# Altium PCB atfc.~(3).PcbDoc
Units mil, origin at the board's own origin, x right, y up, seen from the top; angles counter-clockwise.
Board outline 6000 x 4000 mil, 2 copper layers (Top Layer, Bottom Layer); 22 components, 0 nets, 5638 pads, 0 vias.
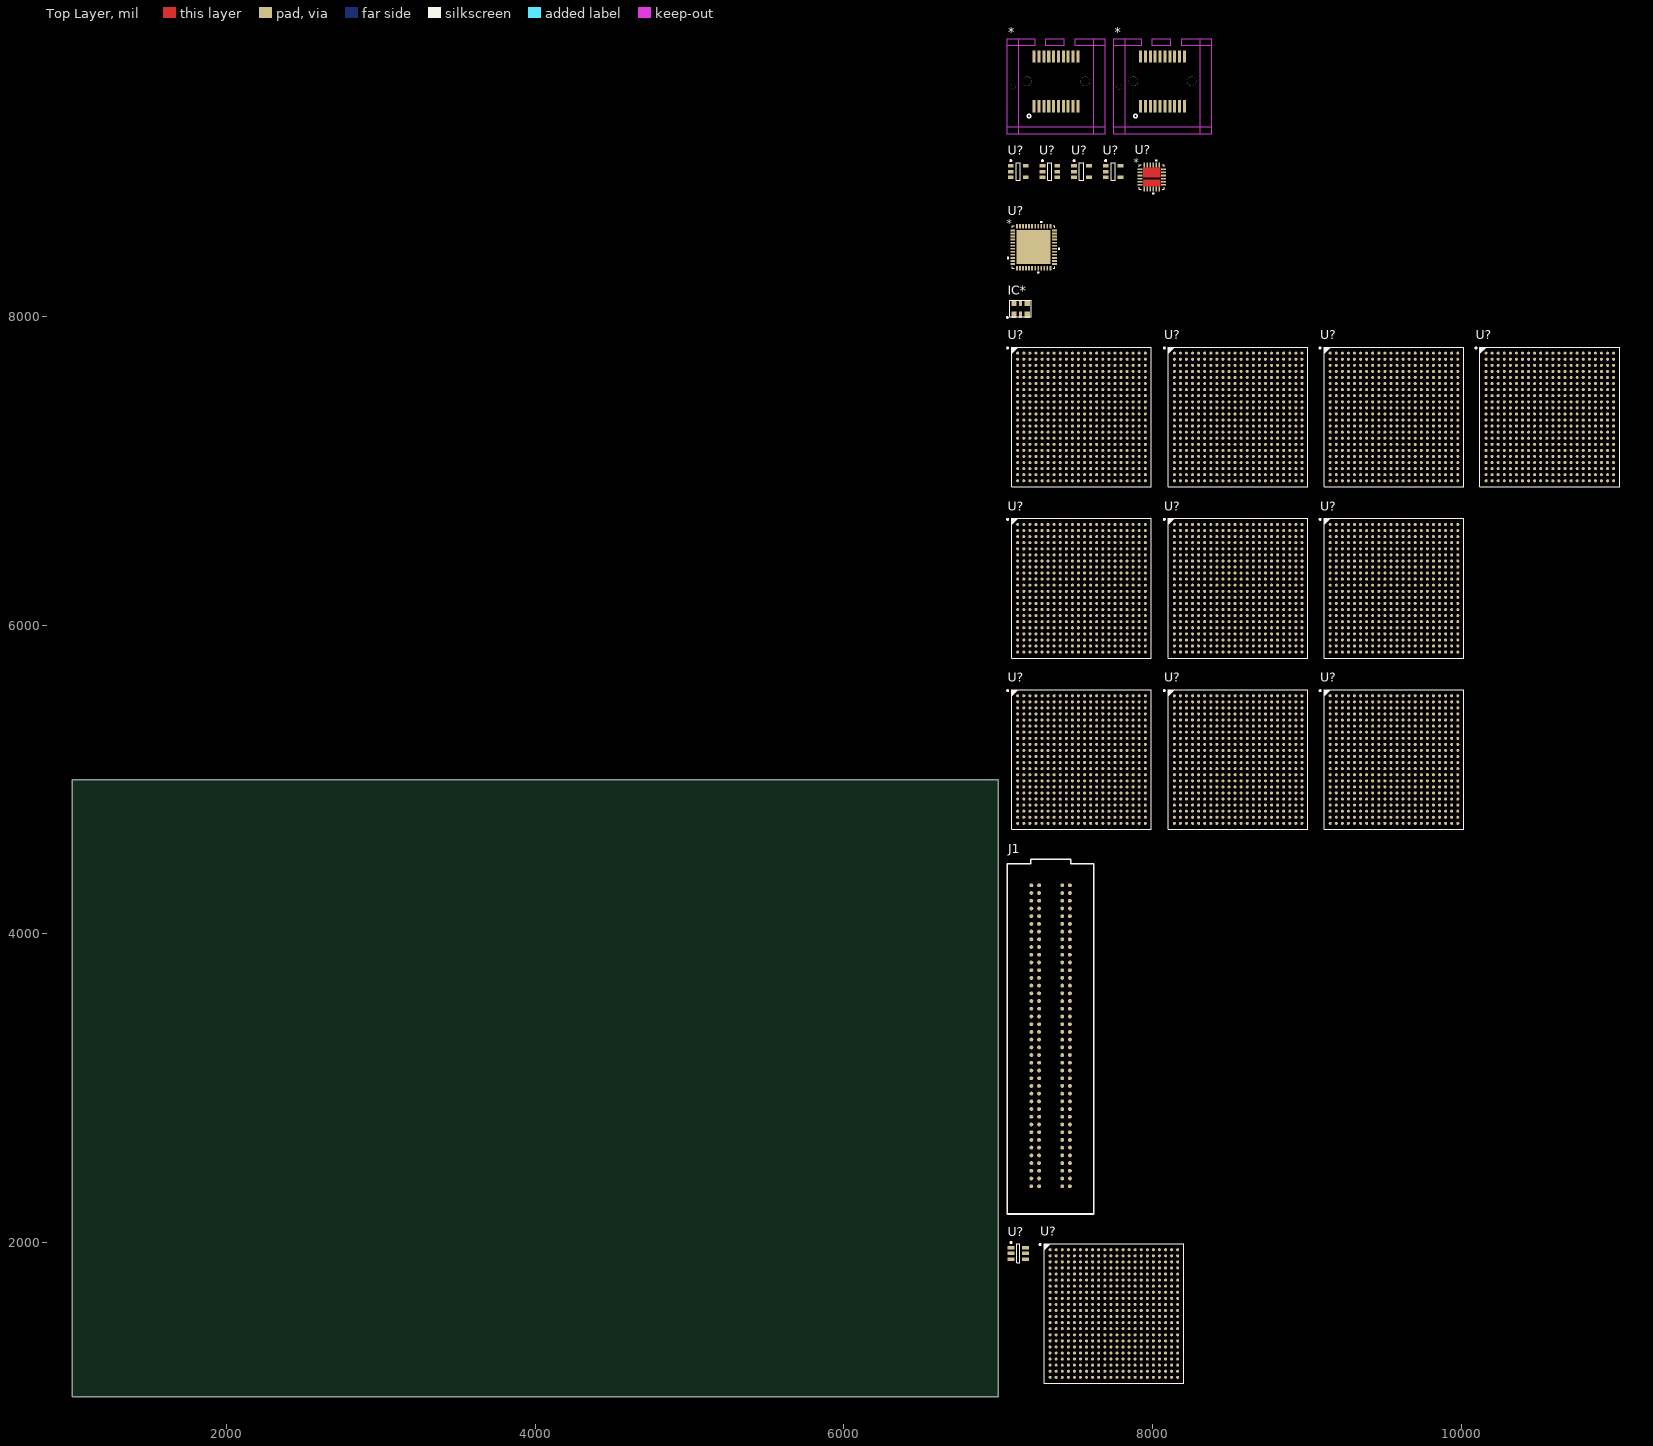
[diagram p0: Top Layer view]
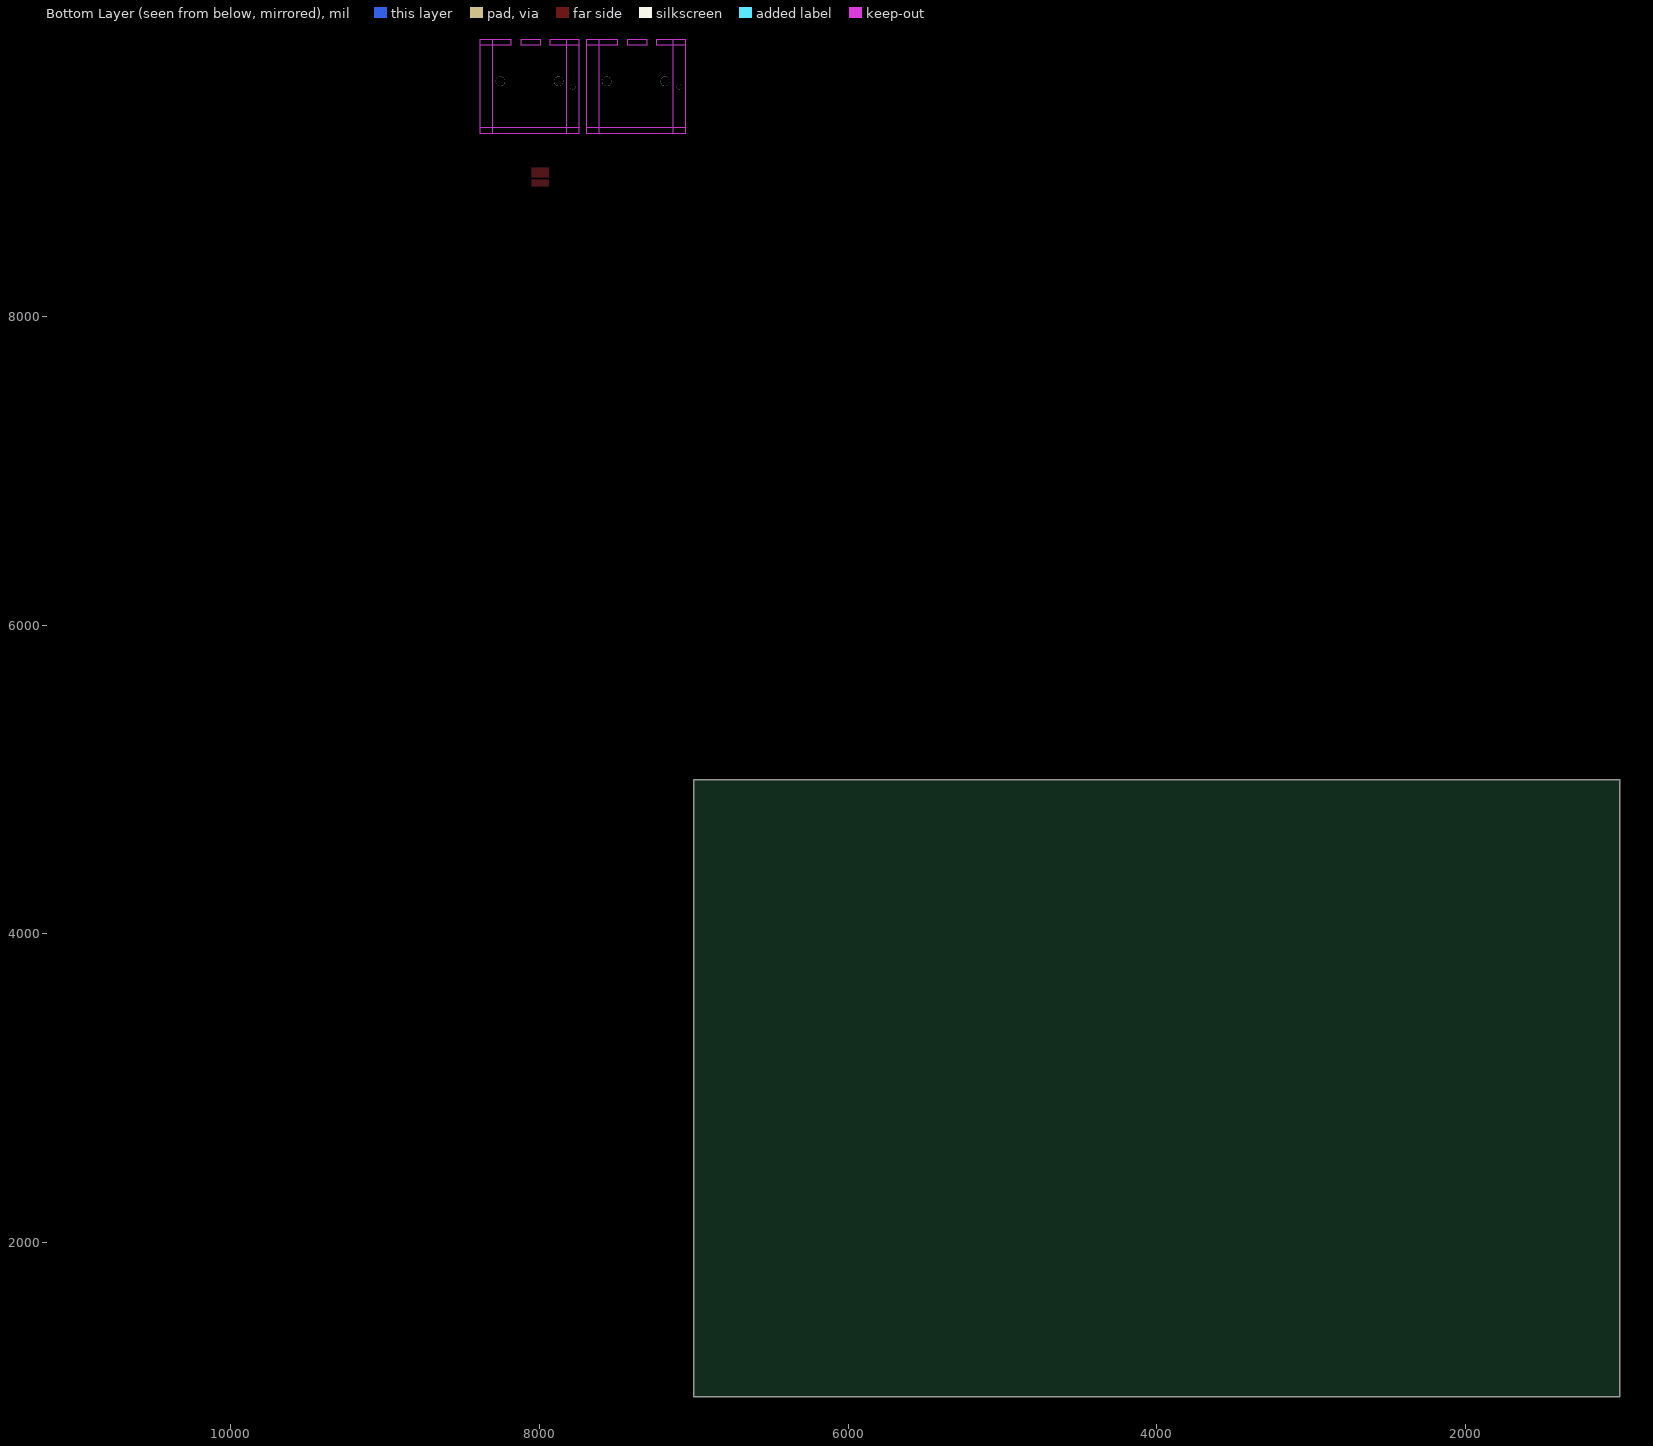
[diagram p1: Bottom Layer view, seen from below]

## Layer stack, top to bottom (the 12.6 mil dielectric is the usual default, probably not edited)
Top Solder: solder mask 0.4, Solder Resist, Dk 3.5
Top Layer: signal copper 1.4
Dielectric 1: dielectric 12.6, FR-4, Dk 4.8
Bottom Layer: signal copper 1.4
Bottom Solder: solder mask 0.4, Solder Resist, Dk 3.5

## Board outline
1000,1000 7000,1000 7000,5000 1000,5000

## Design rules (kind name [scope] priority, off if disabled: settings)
Clearance [All] p1: gap=10 ignorepadtopadclearanceinfootprint=FALSE except(0: Arc-Hole Track-Hole SMDPad-Hole THPad-Hole Via-Hole Fill-Hole Poly-Hole Region-Hole Text-Hole)
PolygonConnect [All] p1: connectstyle=Relief reliefconductorwidth=10 reliefentries=4 polygonreliefangle="90 Angle" airgapwidth=10
RoutingVias [All] p1: holewidth=28 width=50 viastyle="Through Hole" minholewidth=28 minwidth=50 maxholewidth=28 maxwidth=50
SolderMaskExpansion [All] p1: expansion=4
Width [All] p1: maxlimit=10 minlimit=10 preferedwidth=10
30 further rules are at their usual default settings.

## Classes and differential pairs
component class SFP: *
component class Regulators: U?
component class PWR_APD5052: U?
component class IO: IC*
component class FPGA_PWR: U?
component class FPGA_Banks2: U?
component class FPGA_Banks1: U?
component class FMC: J1
component class Config: U?

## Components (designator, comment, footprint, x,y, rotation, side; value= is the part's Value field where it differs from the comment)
* "SFP+" SFP+20 7375,9490 r0 top
* "SFP+" SFP+20 8065,9490 r0 top
IC* "DSC1123CE1-125.0000" DSC1123_32_25 7145,8050 r0 top
J1 "ASP-134603-01" ASP-134603-01 7340,3340 r90 top
U? "24AA025E48T-I/OT" MCHP-SOT-23-OT6_N 7130,1930 r0 top
U? "XC7A35T-1FGG484C" FGG484 7750,1540 r0 top
U? "XC7A35T-1FGG484C" FGG484 7540,5130 r0 top
U? "XC7A35T-1FGG484C" FGG484 8555,5130 r0 top
U? "XC7A35T-1FGG484C" FGG484 9565,5130 r0 top
U? "XC7A35T-1FGG484C" FGG484 8555,6240 r0 top
U? "XC7A35T-1FGG484C" FGG484 9565,6240 r0 top
U? "XC7A35T-1FGG484C" FGG484 7540,6240 r0 top
U? "XC7A35T-1FGG484C" FGG484 9565,7350 r0 top
U? "XC7A35T-1FGG484C" FGG484 8555,7350 r0 top
U? "XC7A35T-1FGG484C" FGG484 7540,7350 r0 top
U? "XC7A35T-1FGG484C" FGG484 10575,7350 r0 top
U? "ADP5052ACPZ-R7" CP_48_13 7230,8450 r0 top value=Value
U? "ADP123AUJZ-R7" ADI-UJ-5_N 7540,8940 r0 top
U? "ADP123AUJZ-R7" ADI-UJ-5_N 7745,8940 r0 top
U? "ADP123AUJZ-R7" ADI-UJ-5_N 7130,8940 r0 top
U? "ADR127BUJZ-REEL7" ADI-UJ-6_N 7335,8940 r0 top
U? "ADP2384ACPZN-R7" CP_24_12 7995,8905 r0 top value=Value

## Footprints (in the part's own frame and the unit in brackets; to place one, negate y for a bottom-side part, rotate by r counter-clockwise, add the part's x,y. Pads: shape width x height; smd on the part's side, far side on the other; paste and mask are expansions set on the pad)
ADI-UJ-5_N [mm] "SOT23, 5-Leads, Body 2.9x1.6mm, Pitch 0.95mm, IPC Medium Density"
  rect 0.95x0.6 smd: 1(-1.225,0.95) 2(-1.225,0) 3(-1.225,-0.95) 4(1.225,-0.95) 5(1.225,0.95)
  silkscreen extent -1.35,-1.45 0.35,1.92, body extent -0.8,-1.45 0.8,1.45, height 1
ADI-UJ-6_N [mm] "SOT23, 6-Leads, Body 2.9x1.6mm, Pitch 0.95mm, IPC Medium Density"
  rect 0.95x0.6 smd: 1(-1.225,0.95) 2(-1.225,0) 3(-1.225,-0.95) 4(1.225,-0.95) 5(1.225,0) 6(1.225,0.95)
  silkscreen extent -1.35,-1.45 0.35,1.92, body extent -0.8,-1.45 0.8,1.45, height 1
ASP-134603-01 [mil]
  round 25 smd paste+5 mask+2: C1(975,-125) C2(925,-125) C3(875,-125) C4(825,-125) C5(775,-125) C6(725,-125) C7(675,-125) C8(625,-125) C9(575,-125) C10(525,-125) C11(475,-125) C12(425,-125) C13(375,-125) C14(325,-125) C15(275,-125) C16(225,-125) C17(175,-125) C18(125,-125) C19(75,-125) C20(25,-125) C21(-25,-125) C22(-75,-125) C23(-125,-125) C24(-175,-125) C25(-225,-125) C26(-275,-125) C27(-325,-125) C28(-375,-125) C29(-425,-125) C30(-475,-125) C31(-525,-125) C32(-575,-125) C33(-625,-125) C34(-675,-125) C35(-725,-125) C36(-775,-125) C37(-825,-125) C38(-875,-125) C39(-925,-125) C40(-975,-125) D1(975,-75) D2(925,-75) D3(875,-75) D4(825,-75) D5(775,-75) D6(725,-75) D7(675,-75) D8(625,-75) D9(575,-75) D10(525,-75) D11(475,-75) D12(425,-75) D13(375,-75) D14(325,-75) D15(275,-75) D16(225,-75) D17(175,-75) D18(125,-75) D19(75,-75) D20(25,-75) D21(-25,-75) D22(-75,-75) D23(-125,-75) D24(-175,-75) D25(-225,-75) D26(-275,-75) D27(-325,-75) D28(-375,-75) D29(-425,-75) D30(-475,-75) D31(-525,-75) D32(-575,-75) D33(-625,-75) D34(-675,-75) D35(-725,-75) D36(-775,-75) D37(-825,-75) D38(-875,-75) D39(-925,-75) D40(-975,-75) G1(975,75) G2(925,75) G3(875,75) G4(825,75) G5(775,75) G6(725,75) G7(675,75) G8(625,75) G9(575,75) G10(525,75) G11(475,75) G12(425,75) G13(375,75) G14(325,75) G15(275,75) G16(225,75) G17(175,75) G18(125,75) G19(75,75) G20(25,75) G21(-25,75) G22(-75,75) G23(-125,75) G24(-175,75) G25(-225,75) G26(-275,75) G27(-325,75) G28(-375,75) G29(-425,75) G30(-475,75) G31(-525,75) G32(-575,75) G33(-625,75) G34(-675,75) G35(-725,75) G36(-775,75) G37(-825,75) G38(-875,75) G39(-925,75) G40(-975,75) H1(975,125) H2(925,125) H3(875,125) H4(825,125) H5(775,125) H6(725,125) H7(675,125) H8(625,125) H9(575,125) H10(525,125) H11(475,125) H12(425,125) H13(375,125) H14(325,125) H15(275,125) H16(225,125) H17(175,125) H18(125,125) H19(75,125) H20(25,125) H21(-25,125) H22(-75,125) H23(-125,125) H24(-175,125) H25(-225,125) H26(-275,125) H27(-325,125) H28(-375,125) H29(-425,125) H30(-475,125) H31(-525,125) H32(-575,125) H33(-625,125) H34(-675,125) H35(-725,125) H36(-775,125) H37(-825,125) H38(-875,125) H39(-925,125) H40(-975,125)
  round 0 hole 50 unplated: MH1(1070.5,-120) MH2(-1070.5,0)
  silkscreen extent -1155,-280 1145,280, body extent -1131,-295 1151,283, height 259
CP_24_12 [mm]
  rect 0.805x0.25 smd: 1(-1.952,1.25) 2(-1.952,0.75) 3(-1.952,0.25) 4(-1.952,-0.25) 5(-1.952,-0.75) 6(-1.952,-1.25) 13(1.952,-1.25) 14(1.952,-0.75) 15(1.952,-0.25) 16(1.952,0.25) 17(1.952,0.75) 18(1.952,1.25)
  rect 0.25x0.805 smd: 7(-1.25,-1.952) 8(-0.75,-1.952) 9(-0.25,-1.952) 10(0.25,-1.952) 11(0.75,-1.952) 12(1.25,-1.952) 19(1.25,1.952) 20(0.75,1.952) 21(0.25,1.952) 22(-0.25,1.952) 23(-0.75,1.952) 24(-1.25,1.952)
  Top Layer region: -1.4,-1.5 -1.4,-0.45 1.4,-0.45 1.4,-1.5
  Top Layer region: -1.4,0 -1.4,1.5 1.4,1.5 1.4,0
  silkscreen extent -2.05,-2.86 2.05,2.86, body extent 0,0 0.25,0.25, height 0.25
CP_48_13 [mm]
  rect 0.755x0.3 smd: 1(-3.433,2.75) 2(-3.433,2.25) 3(-3.433,1.75) 4(-3.433,1.25) 5(-3.433,0.75) 6(-3.433,0.25) 7(-3.433,-0.25) 8(-3.433,-0.75) 9(-3.433,-1.25) 10(-3.433,-1.75) 11(-3.433,-2.25) 12(-3.433,-2.75) 25(3.433,-2.75) 26(3.433,-2.25) 27(3.433,-1.75) 28(3.433,-1.25) 29(3.433,-0.75) 30(3.433,-0.25) 31(3.433,0.25) 32(3.433,0.75) 33(3.433,1.25) 34(3.433,1.75) 35(3.433,2.25) 36(3.433,2.75)
  rect 0.3x0.755 smd: 13(-2.75,-3.433) 14(-2.25,-3.433) 15(-1.75,-3.433) 16(-1.25,-3.433) 17(-0.75,-3.433) 18(-0.25,-3.433) 19(0.25,-3.433) 20(0.75,-3.433) 21(1.25,-3.433) 22(1.75,-3.433) 23(2.25,-3.433) 24(2.75,-3.433) 37(2.75,3.433) 38(2.25,3.433) 39(1.75,3.433) 40(1.25,3.433) 41(0.75,3.433) 42(0.25,3.433) 43(-0.25,3.433) 44(-0.75,3.433) 45(-1.25,3.433) 46(-1.75,3.433) 47(-2.25,3.433) 48(-2.75,3.433)
  rect 5.6x5.6 smd mask-2.781: 49(0,0)
  silkscreen extent -4.32,-4.32 4.32,4.32, body extent 0,0 0.25,0.25, height 0.25
DSC1123_32_25 [mm]
  rect 0.9x1 smd: 1(-1.075,-0.95) 3(1.075,-0.95) 4(1.075,0.95) 6(-1.075,0.95)
  rect 0.5x1 smd: 2(0,-0.95) 5(0,0.95)
  silkscreen extent -2.26,-1.5 1.78,1.4, body extent -1.78,-1.27 1.78,1.4, height 0.85
FGG484 [mm] "BGA, 484-Balls, Body 23x23mm, Pitch 1mm"
  round 0.5 smd: A1(-10.5,10.5) A2(-9.5,10.5) A3(-8.5,10.5) A4(-7.5,10.5) A5(-6.5,10.5) A6(-5.5,10.5) A7(-4.5,10.5) A8(-3.5,10.5) A9(-2.5,10.5) A10(-1.5,10.5) A11(-0.5,10.5) A12(0.5,10.5) A13(1.5,10.5) A14(2.5,10.5) A15(3.5,10.5) A16(4.5,10.5) A17(5.5,10.5) A18(6.5,10.5) A19(7.5,10.5) A20(8.5,10.5) A21(9.5,10.5) A22(10.5,10.5) AA1(-10.5,-9.5) AA2(-9.5,-9.5) AA3(-8.5,-9.5) AA4(-7.5,-9.5) AA5(-6.5,-9.5) AA6(-5.5,-9.5) AA7(-4.5,-9.5) AA8(-3.5,-9.5) AA9(-2.5,-9.5) AA10(-1.5,-9.5) AA11(-0.5,-9.5) AA12(0.5,-9.5) AA13(1.5,-9.5) AA14(2.5,-9.5) AA15(3.5,-9.5) AA16(4.5,-9.5) AA17(5.5,-9.5) AA18(6.5,-9.5) AA19(7.5,-9.5) AA20(8.5,-9.5) AA21(9.5,-9.5) AA22(10.5,-9.5) AB1(-10.5,-10.5) AB2(-9.5,-10.5) AB3(-8.5,-10.5) AB4(-7.5,-10.5) AB5(-6.5,-10.5) AB6(-5.5,-10.5) AB7(-4.5,-10.5) AB8(-3.5,-10.5) AB9(-2.5,-10.5) AB10(-1.5,-10.5) AB11(-0.5,-10.5) AB12(0.5,-10.5) AB13(1.5,-10.5) AB14(2.5,-10.5) AB15(3.5,-10.5) AB16(4.5,-10.5) AB17(5.5,-10.5) AB18(6.5,-10.5) AB19(7.5,-10.5) AB20(8.5,-10.5) AB21(9.5,-10.5) AB22(10.5,-10.5) B1(-10.5,9.5) B2(-9.5,9.5) B3(-8.5,9.5) B4(-7.5,9.5) B5(-6.5,9.5) B6(-5.5,9.5) B7(-4.5,9.5) B8(-3.5,9.5) B9(-2.5,9.5) B10(-1.5,9.5) B11(-0.5,9.5) B12(0.5,9.5) B13(1.5,9.5) B14(2.5,9.5) B15(3.5,9.5) B16(4.5,9.5) B17(5.5,9.5) B18(6.5,9.5) B19(7.5,9.5) B20(8.5,9.5) B21(9.5,9.5) B22(10.5,9.5) C1(-10.5,8.5) C2(-9.5,8.5) C3(-8.5,8.5) C4(-7.5,8.5) C5(-6.5,8.5) C6(-5.5,8.5) C7(-4.5,8.5) C8(-3.5,8.5) C9(-2.5,8.5) C10(-1.5,8.5) C11(-0.5,8.5) C12(0.5,8.5) C13(1.5,8.5) C14(2.5,8.5) C15(3.5,8.5) C16(4.5,8.5) C17(5.5,8.5) C18(6.5,8.5) C19(7.5,8.5) C20(8.5,8.5) C21(9.5,8.5) C22(10.5,8.5) D1(-10.5,7.5) D2(-9.5,7.5) D3(-8.5,7.5) D4(-7.5,7.5) D5(-6.5,7.5) D6(-5.5,7.5) D7(-4.5,7.5) D8(-3.5,7.5) D9(-2.5,7.5) D10(-1.5,7.5) D11(-0.5,7.5) D12(0.5,7.5) D13(1.5,7.5) D14(2.5,7.5) D15(3.5,7.5) D16(4.5,7.5) D17(5.5,7.5) D18(6.5,7.5) D19(7.5,7.5) D20(8.5,7.5) D21(9.5,7.5) D22(10.5,7.5) E1(-10.5,6.5) E2(-9.5,6.5) E3(-8.5,6.5) E4(-7.5,6.5) E5(-6.5,6.5) E6(-5.5,6.5) E7(-4.5,6.5) E8(-3.5,6.5) E9(-2.5,6.5) E10(-1.5,6.5) E11(-0.5,6.5) E12(0.5,6.5) E13(1.5,6.5) E14(2.5,6.5) E15(3.5,6.5) E16(4.5,6.5) E17(5.5,6.5) E18(6.5,6.5) E19(7.5,6.5) E20(8.5,6.5) E21(9.5,6.5) E22(10.5,6.5) F1(-10.5,5.5) F2(-9.5,5.5) F3(-8.5,5.5) F4(-7.5,5.5) F5(-6.5,5.5) F6(-5.5,5.5) F7(-4.5,5.5) F8(-3.5,5.5) F9(-2.5,5.5) F10(-1.5,5.5) F11(-0.5,5.5) F12(0.5,5.5) F13(1.5,5.5) F14(2.5,5.5) F15(3.5,5.5) F16(4.5,5.5) F17(5.5,5.5) F18(6.5,5.5) F19(7.5,5.5) F20(8.5,5.5) F21(9.5,5.5) F22(10.5,5.5) G1(-10.5,4.5) G2(-9.5,4.5) G3(-8.5,4.5) G4(-7.5,4.5) G5(-6.5,4.5) G6(-5.5,4.5) G7(-4.5,4.5) G8(-3.5,4.5) G9(-2.5,4.5) G10(-1.5,4.5) G11(-0.5,4.5) G12(0.5,4.5) G13(1.5,4.5) G14(2.5,4.5) G15(3.5,4.5) G16(4.5,4.5) G17(5.5,4.5) G18(6.5,4.5) G19(7.5,4.5) G20(8.5,4.5) G21(9.5,4.5) G22(10.5,4.5) H1(-10.5,3.5) H2(-9.5,3.5) H3(-8.5,3.5) H4(-7.5,3.5) H5(-6.5,3.5) H6(-5.5,3.5) H7(-4.5,3.5) H8(-3.5,3.5) H9(-2.5,3.5) H10(-1.5,3.5) H11(-0.5,3.5) H12(0.5,3.5) H13(1.5,3.5) H14(2.5,3.5) H15(3.5,3.5) H16(4.5,3.5) H17(5.5,3.5) H18(6.5,3.5) H19(7.5,3.5) H20(8.5,3.5) H21(9.5,3.5) H22(10.5,3.5) J1(-10.5,2.5) J2(-9.5,2.5) J3(-8.5,2.5) J4(-7.5,2.5) J5(-6.5,2.5) J6(-5.5,2.5) J7(-4.5,2.5) J8(-3.5,2.5) J9(-2.5,2.5) J10(-1.5,2.5) J11(-0.5,2.5) J12(0.5,2.5) J13(1.5,2.5) J14(2.5,2.5) J15(3.5,2.5) J16(4.5,2.5) J17(5.5,2.5) J18(6.5,2.5) J19(7.5,2.5) J20(8.5,2.5) J21(9.5,2.5) J22(10.5,2.5) K1(-10.5,1.5) K2(-9.5,1.5) K3(-8.5,1.5) K4(-7.5,1.5) K5(-6.5,1.5) K6(-5.5,1.5) K7(-4.5,1.5) K8(-3.5,1.5) K9(-2.5,1.5) K10(-1.5,1.5) K11(-0.5,1.5) K12(0.5,1.5) K13(1.5,1.5) K14(2.5,1.5) K15(3.5,1.5) K16(4.5,1.5) K17(5.5,1.5) K18(6.5,1.5) K19(7.5,1.5) K20(8.5,1.5) K21(9.5,1.5) K22(10.5,1.5) L1(-10.5,0.5) L2(-9.5,0.5) L3(-8.5,0.5) L4(-7.5,0.5) L5(-6.5,0.5) L6(-5.5,0.5) L7(-4.5,0.5) L8(-3.5,0.5) L9(-2.5,0.5) L10(-1.5,0.5) L11(-0.5,0.5) L12(0.5,0.5) L13(1.5,0.5) L14(2.5,0.5) L15(3.5,0.5) L16(4.5,0.5) L17(5.5,0.5) L18(6.5,0.5) L19(7.5,0.5) L20(8.5,0.5) L21(9.5,0.5) L22(10.5,0.5) M1(-10.5,-0.5) M2(-9.5,-0.5) M3(-8.5,-0.5) M4(-7.5,-0.5) M5(-6.5,-0.5) M6(-5.5,-0.5) M7(-4.5,-0.5) M8(-3.5,-0.5) M9(-2.5,-0.5) M10(-1.5,-0.5) M11(-0.5,-0.5) M12(0.5,-0.5) M13(1.5,-0.5) M14(2.5,-0.5) M15(3.5,-0.5) M16(4.5,-0.5) M17(5.5,-0.5) M18(6.5,-0.5) M19(7.5,-0.5) M20(8.5,-0.5) M21(9.5,-0.5) M22(10.5,-0.5) N1(-10.5,-1.5) N2(-9.5,-1.5) N3(-8.5,-1.5) N4(-7.5,-1.5) N5(-6.5,-1.5) N6(-5.5,-1.5) N7(-4.5,-1.5) N8(-3.5,-1.5) N9(-2.5,-1.5) N10(-1.5,-1.5) N11(-0.5,-1.5) N12(0.5,-1.5) N13(1.5,-1.5) N14(2.5,-1.5) N15(3.5,-1.5) N16(4.5,-1.5) N17(5.5,-1.5) N18(6.5,-1.5) N19(7.5,-1.5) N20(8.5,-1.5) N21(9.5,-1.5) N22(10.5,-1.5) P1(-10.5,-2.5) P2(-9.5,-2.5) P3(-8.5,-2.5) P4(-7.5,-2.5) P5(-6.5,-2.5) P6(-5.5,-2.5) P7(-4.5,-2.5) P8(-3.5,-2.5) P9(-2.5,-2.5) P10(-1.5,-2.5) P11(-0.5,-2.5) P12(0.5,-2.5) P13(1.5,-2.5) P14(2.5,-2.5) P15(3.5,-2.5) P16(4.5,-2.5) P17(5.5,-2.5) P18(6.5,-2.5) P19(7.5,-2.5) P20(8.5,-2.5) P21(9.5,-2.5) P22(10.5,-2.5) R1(-10.5,-3.5) R2(-9.5,-3.5) R3(-8.5,-3.5) R4(-7.5,-3.5) R5(-6.5,-3.5) R6(-5.5,-3.5) R7(-4.5,-3.5) R8(-3.5,-3.5) R9(-2.5,-3.5) R10(-1.5,-3.5) R11(-0.5,-3.5) R12(0.5,-3.5) R13(1.5,-3.5) R14(2.5,-3.5) R15(3.5,-3.5) R16(4.5,-3.5) R17(5.5,-3.5) R18(6.5,-3.5) R19(7.5,-3.5) R20(8.5,-3.5) R21(9.5,-3.5) R22(10.5,-3.5) T1(-10.5,-4.5) T2(-9.5,-4.5) T3(-8.5,-4.5) T4(-7.5,-4.5) T5(-6.5,-4.5) T6(-5.5,-4.5) T7(-4.5,-4.5) T8(-3.5,-4.5) T9(-2.5,-4.5) T10(-1.5,-4.5) T11(-0.5,-4.5) T12(0.5,-4.5) T13(1.5,-4.5) T14(2.5,-4.5) T15(3.5,-4.5) T16(4.5,-4.5) T17(5.5,-4.5) T18(6.5,-4.5) T19(7.5,-4.5) T20(8.5,-4.5) T21(9.5,-4.5) T22(10.5,-4.5) U1(-10.5,-5.5) U2(-9.5,-5.5) U3(-8.5,-5.5) U4(-7.5,-5.5) U5(-6.5,-5.5) U6(-5.5,-5.5) U7(-4.5,-5.5) U8(-3.5,-5.5) U9(-2.5,-5.5) U10(-1.5,-5.5) U11(-0.5,-5.5) U12(0.5,-5.5) U13(1.5,-5.5) U14(2.5,-5.5) U15(3.5,-5.5) U16(4.5,-5.5) U17(5.5,-5.5) U18(6.5,-5.5) U19(7.5,-5.5) U20(8.5,-5.5) U21(9.5,-5.5) U22(10.5,-5.5) V1(-10.5,-6.5) V2(-9.5,-6.5) V3(-8.5,-6.5) V4(-7.5,-6.5) V5(-6.5,-6.5) V6(-5.5,-6.5) V7(-4.5,-6.5) V8(-3.5,-6.5) V9(-2.5,-6.5) V10(-1.5,-6.5) V11(-0.5,-6.5) V12(0.5,-6.5) V13(1.5,-6.5) V14(2.5,-6.5) V15(3.5,-6.5) V16(4.5,-6.5) V17(5.5,-6.5) V18(6.5,-6.5) V19(7.5,-6.5) V20(8.5,-6.5) V21(9.5,-6.5) V22(10.5,-6.5) W1(-10.5,-7.5) W2(-9.5,-7.5) W3(-8.5,-7.5) W4(-7.5,-7.5) W5(-6.5,-7.5) W6(-5.5,-7.5) W7(-4.5,-7.5) W8(-3.5,-7.5) W9(-2.5,-7.5) W10(-1.5,-7.5) W11(-0.5,-7.5) W12(0.5,-7.5) W13(1.5,-7.5) W14(2.5,-7.5) W15(3.5,-7.5) W16(4.5,-7.5) W17(5.5,-7.5) W18(6.5,-7.5) W19(7.5,-7.5) W20(8.5,-7.5) W21(9.5,-7.5) W22(10.5,-7.5) Y1(-10.5,-8.5) Y2(-9.5,-8.5) Y3(-8.5,-8.5) Y4(-7.5,-8.5) Y5(-6.5,-8.5) Y6(-5.5,-8.5) Y7(-4.5,-8.5) Y8(-3.5,-8.5) Y9(-2.5,-8.5) Y10(-1.5,-8.5) Y11(-0.5,-8.5) Y12(0.5,-8.5) Y13(1.5,-8.5) Y14(2.5,-8.5) Y15(3.5,-8.5) Y16(4.5,-8.5) Y17(5.5,-8.5) Y18(6.5,-8.5) Y19(7.5,-8.5) Y20(8.5,-8.5) Y21(9.5,-8.5) Y22(10.5,-8.5)
  silkscreen extent -12.27,-11.5 11.5,11.5, body extent -11.5,-11.5 11.5,11.5, height 2.6
MCHP-SOT-23-OT6_N [mm] "SOT23, 6-Leads, Body 2.9x1.55mm, Pitch 0.95mm, IPC Medium Density"
  rect 1.1x0.6 smd: 1(-1.2,0.95) 2(-1.2,0) 3(-1.2,-0.95) 4(1.2,-0.95) 5(1.2,0) 6(1.2,0.95)
  silkscreen extent -1.32,-1.55 0.25,1.92, body extent -0.9,-1.55 0.9,1.55, height 1.45
SFP+20 [mm]
  rect 0.5x2 smd: 1(-3.6,-3.2) 2(-2.8,-3.2) 3(-2,-3.2) 4(-1.2,-3.2) 5(-0.4,-3.2) 6(0.4,-3.2) 7(1.2,-3.2) 8(2,-3.2) 9(2.8,-3.2) 10(3.6,-3.2) 11(3.6,5) 12(2.8,5) 13(2,5) 14(1.2,5) 15(0.4,5) 16(-0.4,5) 17(-1.2,5) 18(-2,5) 19(-2.8,5) 20(-3.6,5)
  round 0.85 hole 0.85 paste+0 mask+0: ""(-7.13,0)
  round 1.55 hole 1.55 paste+0 mask+0: ""(-4.8,0.9) ""(4.8,0.9)
  Keep-Out Layer region: 3.05,6.8 8.12,6.8 8.12,7.8 3.05,7.8
  Keep-Out Layer region: -8.13,6.8 -3.45,6.8 -3.45,7.8 -8.13,7.8
  Keep-Out Layer region: -8.13,-7.7 8.13,-7.7 8.13,-6.7 -8.13,-6.7
  Keep-Out Layer region: -1.75,6.8 1.35,6.8 1.35,7.8 -1.75,7.8
  Keep-Out Layer region: 6.13,-7.7 8.12,-7.7 8.12,7.8 6.13,7.8
  Keep-Out Layer region: -8.13,-7.7 -6.13,-7.7 -6.13,7.8 -8.13,7.8
  silkscreen extent -4.73,-5.11 -4.16,-4.54

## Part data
IC*: library part DSC1123CE1-125, "Standard Clock Oscillators Oscillator Hi Perf -20C-70C 50ppm"
J1: "0.050\" PITCH SOCKET ARRAY ASSEMBLY.", MANUFACTURER=SAMTEC
U?: "2K bits I2C™ Serial EEPROM with EUI-48™ Node Identity, 1.7 to 5.5 V, 400 kHz, -40 to 85 degC, 6-pin SOT-23 (OT6), Tape and Reel", MANUFACTURER=Microchip, Supplier Part Number 1=24AA025E48T-I/OTTR-ND
U? U? U? U? U? U? U? U? U? U? U?: "Artix-7 FPGA, 250 User I/Os, 4 GTP, 484-Ball BGA, Speed Grade 1, Commercial Grade, Pb-Free", MANUFACTURER=Xilinx, Operating Temperature Range=Commercial
U? U?: "Imported"
U? U? U?: "300 mA, Low Quiescent Current, CMOS Linear Regulator, 2.3 to 5.5 V Vin, 0.8 to 5 V Vout, Industrial, 5-pin SOT23 (UJ-5), Reel", MANUFACTURER="Analog Devices", Supplier Part Number 1=ADP123AUJZ-R7TR-ND, Supply Current IGND @ Small Load=45uA
U?: "Precision, Micropower LDO Voltage Reference in TSOT, 1.25 V Output, 2.7 to 18 V Supply, Industrial, 6-pin SOT23 (UJ-6), Reel", MANUFACTURER="Analog Devices", Operating Temp Range="-40 to 125 degC", Supplier Part Number 1=ADR127BUJZ-REEL7TR-ND

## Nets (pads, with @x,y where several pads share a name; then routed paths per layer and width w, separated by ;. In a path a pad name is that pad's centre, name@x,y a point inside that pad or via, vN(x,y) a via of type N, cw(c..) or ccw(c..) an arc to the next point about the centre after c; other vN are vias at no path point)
pads on no net: *. *.1 *.2 *.3 *.4 *.5 *.6 *.7 *.8 *.9 *.10 *.11 *.12 *.13 *.14 *.15 *.16 *.17 *.18 *.19 *.20 IC*.1 IC*.2 IC*.3 IC*.4 IC*.5 IC*.6 J1.C1 J1.C2 J1.C3 J1.C4 J1.C5 J1.C6 J1.C7 J1.C8 J1.C9 J1.C10 J1.C11 J1.C12 J1.C13 J1.C14 J1.C15 J1.C16 J1.C17 J1.C18 J1.C19 J1.C20 J1.C21 J1.C22 J1.C23 J1.C24 J1.C25 J1.C26 J1.C27 J1.C28 J1.C29 J1.C30 J1.C31 J1.C32 J1.C33 J1.C34 J1.C35 J1.C36 J1.C37 J1.C38 J1.C39 J1.C40 J1.D1 J1.D2 J1.D3 J1.D4 J1.D5 J1.D6 J1.D7 J1.D8 J1.D9 J1.D10 J1.D11 J1.D12 J1.D13 J1.D14 J1.D15 J1.D16 J1.D17 J1.D18 J1.D19 J1.D20 J1.D21 J1.D22 J1.D23 J1.D24 J1.D25 J1.D26 J1.D27 J1.D28 J1.D29 J1.D30 J1.D31 J1.D32 J1.D33 J1.D34 J1.D35 J1.D36 J1.D37 J1.D38 J1.D39 J1.D40 J1.G1 J1.G2 J1.G3 J1.G4 J1.G5 J1.G6 J1.G7 J1.G8 J1.G9 J1.G10 J1.G11 J1.G12 J1.G13 J1.G14 J1.G15 J1.G16 J1.G17 J1.G18 J1.G19 J1.G20 J1.G21 J1.G22 J1.G23 J1.G24 J1.G25 J1.G26 J1.G27 J1.G28 J1.G29 J1.G30 J1.G31 J1.G32 J1.G33 J1.G34 J1.G35 J1.G36 J1.G37 J1.G38 J1.G39 J1.G40 J1.H1 J1.H2 J1.H3 J1.H4 J1.H5 J1.H6 J1.H7 J1.H8 J1.H9 J1.H10 J1.H11 J1.H12 J1.H13 J1.H14 J1.H15 J1.H16 J1.H17 J1.H18 J1.H19 J1.H20 J1.H21 J1.H22 J1.H23 J1.H24 J1.H25 J1.H26 J1.H27 J1.H28 J1.H29 J1.H30 J1.H31 J1.H32 J1.H33 J1.H34 J1.H35 J1.H36 J1.H37 J1.H38 J1.H39 J1.H40 J1.MH1 J1.MH2 U?.1 U?.2 U?.3 U?.4 U?.5 U?.6 U?.7 U?.8 U?.9 U?.10 U?.11 U?.12 U?.13 U?.14 U?.15 U?.16 U?.17 U?.18 U?.19 U?.20 U?.21 U?.22 U?.23 U?.24 U?.25 U?.26 U?.27 U?.28 U?.29 U?.30 U?.31 U?.32 U?.33 U?.34 U?.35 U?.36 U?.37 U?.38 U?.39 U?.40 U?.41 U?.42 U?.43 U?.44 U?.45 U?.46 U?.47 U?.48 U?.49 U?.A1 U?.A2 U?.A3 U?.A4 U?.A5 U?.A6 U?.A7 U?.A8 U?.A9 U?.A10 U?.A11 U?.A12 U?.A13 U?.A14 U?.A15 U?.A16 U?.A17 U?.A18 U?.A19 U?.A20 U?.A21 U?.A22 U?.AA1 U?.AA2 U?.AA3 U?.AA4 U?.AA5 U?.AA6 U?.AA7 U?.AA8 U?.AA9 U?.AA10 U?.AA11 U?.AA12 U?.AA13 U?.AA14 U?.AA15 U?.AA16 U?.AA17 U?.AA18 U?.AA19 U?.AA20 U?.AA21 U?.AA22 U?.AB1 U?.AB2 U?.AB3 U?.AB4 U?.AB5 U?.AB6 U?.AB7 U?.AB8 U?.AB9 U?.AB10 U?.AB11 U?.AB12 U?.AB13 U?.AB14 U?.AB15 U?.AB16 U?.AB17 U?.AB18 U?.AB19 U?.AB20 U?.AB21 U?.AB22 U?.B1 U?.B2 U?.B3 U?.B4 U?.B5 U?.B6 U?.B7 U?.B8 U?.B9 U?.B10 U?.B11 U?.B12 U?.B13 U?.B14 U?.B15 U?.B16 U?.B17 U?.B18 U?.B19 U?.B20 U?.B21 U?.B22 U?.C1 U?.C2 U?.C3 U?.C4 U?.C5 U?.C6 U?.C7 U?.C8 U?.C9 U?.C10 U?.C11 U?.C12 U?.C13 U?.C14 U?.C15 U?.C16 U?.C17 U?.C18 U?.C19 U?.C20 U?.C21 U?.C22 U?.D1 U?.D2 U?.D3 U?.D4 U?.D5 U?.D6 U?.D7 U?.D8 U?.D9 U?.D10 U?.D11 U?.D12 U?.D13 U?.D14 U?.D15 U?.D16 U?.D17 U?.D18 U?.D19 U?.D20 U?.D21 U?.D22 U?.E1 U?.E2 U?.E3 U?.E4 U?.E5 U?.E6 U?.E7 U?.E8 U?.E9 U?.E10 U?.E11 U?.E12 U?.E13 U?.E14 U?.E15 U?.E16 U?.E17 U?.E18 U?.E19 U?.E20 U?.E21 U?.E22 U?.F1 U?.F2 U?.F3 U?.F4 U?.F5 U?.F6 U?.F7 U?.F8 U?.F9 U?.F10 U?.F11 U?.F12 U?.F13 U?.F14 U?.F15 U?.F16 U?.F17 U?.F18 U?.F19 U?.F20 U?.F21 U?.F22 U?.G1 U?.G2 U?.G3 U?.G4 U?.G5 U?.G6 U?.G7 U?.G8 U?.G9 U?.G10 U?.G11 U?.G12 U?.G13 U?.G14 U?.G15 U?.G16 U?.G17 U?.G18 U?.G19 U?.G20 U?.G21 U?.G22 U?.H1 U?.H2 U?.H3 U?.H4 U?.H5 U?.H6 U?.H7 U?.H8 U?.H9 U?.H10 U?.H11 U?.H12 U?.H13 U?.H14 U?.H15 U?.H16 U?.H17 U?.H18 U?.H19 U?.H20 U?.H21 U?.H22 U?.J1 U?.J2 U?.J3 U?.J4 U?.J5 U?.J6 U?.J7 U?.J8 U?.J9 U?.J10 U?.J11 U?.J12 U?.J13 U?.J14 U?.J15 U?.J16 U?.J17 U?.J18 U?.J19 U?.J20 U?.J21 U?.J22 U?.K1 U?.K2 U?.K3 U?.K4 U?.K5 U?.K6 U?.K7 U?.K8 U?.K9 U?.K10 U?.K11 U?.K12 U?.K13 U?.K14 U?.K15 U?.K16 U?.K17 U?.K18 U?.K19 U?.K20 U?.K21 U?.K22 U?.L1 U?.L2 U?.L3 U?.L4 U?.L5 U?.L6 U?.L7 U?.L8 U?.L9 U?.L10 U?.L11 U?.L12 U?.L13 U?.L14 U?.L15 U?.L16 U?.L17 U?.L18 U?.L19 U?.L20 U?.L21 U?.L22 U?.M1 U?.M2 U?.M3 U?.M4 U?.M5 U?.M6 U?.M7 U?.M8 U?.M9 U?.M10 U?.M11 U?.M12 U?.M13 U?.M14 U?.M15 U?.M16 U?.M17 U?.M18 U?.M19 U?.M20 U?.M21 U?.M22 U?.N1 U?.N2 U?.N3 U?.N4 U?.N5 U?.N6 U?.N7 U?.N8 U?.N9 U?.N10 U?.N11 U?.N12 U?.N13 U?.N14 U?.N15 U?.N16 U?.N17 U?.N18 U?.N19 U?.N20 U?.N21 U?.N22 U?.P1 U?.P2 U?.P3 U?.P4 U?.P5 U?.P6 U?.P7 U?.P8 U?.P9 U?.P10 U?.P11 U?.P12 U?.P13 U?.P14 U?.P15 U?.P16 U?.P17 U?.P18 U?.P19 U?.P20 U?.P21 U?.P22 U?.R1 U?.R2 U?.R3 U?.R4 U?.R5 U?.R6 U?.R7 U?.R8 U?.R9 U?.R10 U?.R11 U?.R12 U?.R13 U?.R14 U?.R15 U?.R16 U?.R17 U?.R18 U?.R19 U?.R20 U?.R21 U?.R22 U?.T1 U?.T2 U?.T3 U?.T4 U?.T5 U?.T6 U?.T7 U?.T8 U?.T9 U?.T10 U?.T11 U?.T12 U?.T13 U?.T14 U?.T15 U?.T16 U?.T17 U?.T18 U?.T19 U?.T20 U?.T21 U?.T22 U?.U1 U?.U2 U?.U3 U?.U4 U?.U5 U?.U6 U?.U7 U?.U8 U?.U9 U?.U10 U?.U11 U?.U12 U?.U13 U?.U14 U?.U15 U?.U16 U?.U17 U?.U18 U?.U19 U?.U20 U?.U21 U?.U22 U?.V1 U?.V2 U?.V3 U?.V4 U?.V5 U?.V6 U?.V7 U?.V8 U?.V9 U?.V10 U?.V11 U?.V12 U?.V13 U?.V14 U?.V15 U?.V16 U?.V17 U?.V18 U?.V19 U?.V20 U?.V21 U?.V22 U?.W1 U?.W2 U?.W3 U?.W4 U?.W5 U?.W6 U?.W7 U?.W8 U?.W9 U?.W10 U?.W11 U?.W12 U?.W13 U?.W14 U?.W15 U?.W16 U?.W17 U?.W18 U?.W19 U?.W20 U?.W21 U?.W22 U?.Y1 U?.Y2 U?.Y3 U?.Y4 U?.Y5 U?.Y6 U?.Y7 U?.Y8 U?.Y9 U?.Y10 U?.Y11 U?.Y12 U?.Y13 U?.Y14 U?.Y15 U?.Y16 U?.Y17 U?.Y18 U?.Y19 U?.Y20 U?.Y21 U?.Y22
